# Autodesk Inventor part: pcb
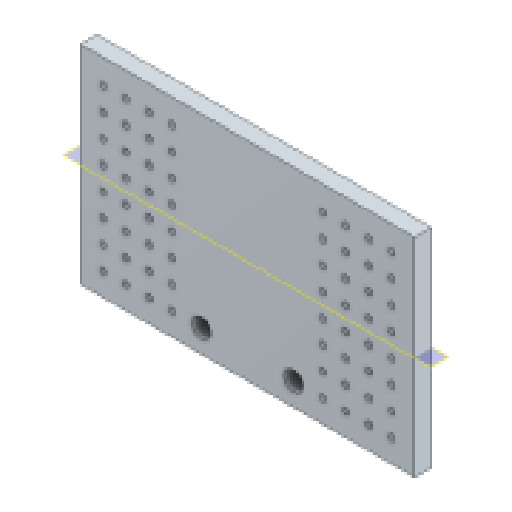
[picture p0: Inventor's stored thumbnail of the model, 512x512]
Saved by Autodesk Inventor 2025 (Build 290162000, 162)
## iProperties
Created: 2025-05
Part Number: pcb
Material: Generico
Document SubType Name: Modeling
Designer: R5800u
Density: 1 g/cm^3
Appearance: Default
Author: R5800u
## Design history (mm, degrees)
feature "Base1"
node "Piano di lavoro1"
node "Solido1"
